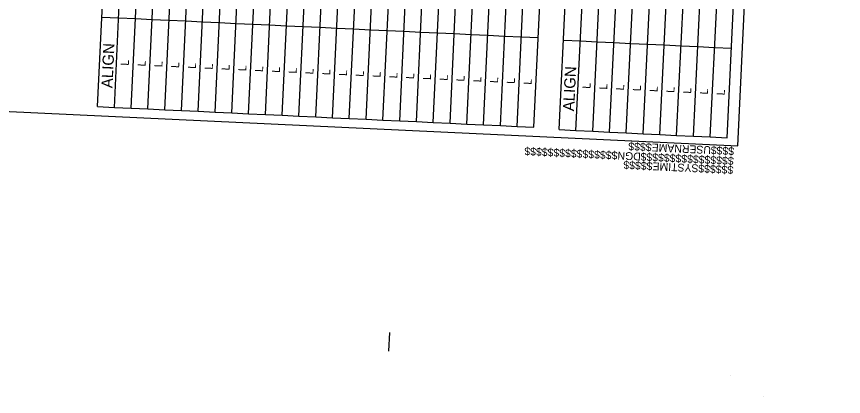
# Model space of a CAD drawing. Extents: x 2167298 to 2168977, y 841960 to 844561.
# Drawn here: x 2168145 to 2168977, y 841960 to 842342 of the extents above; entities that cross this region are included whole.
import ezdxf

# ---------------------------------------------------------------- set-up
doc = ezdxf.new("R2010")
doc.units = 0
for name, color, linetype in [('CTL Sheet Border CELL', 7, 'Continuous'), ('CTL Sheet Notes CELL', 7, 'Continuous'), ('CTL Sheet Table Cell', 7, 'Continuous'), ('CTL Sheet Text', 7, 'Continuous'), ('Sheet Title CELL', 7, 'Continuous')]:
    doc.layers.add(name, color=color, linetype=linetype)

msp = doc.modelspace()

# ---------------------------------------------------------------- linework, layer by layer
at = {"layer": 'CTL Sheet Border CELL'}
for p, q in [((2168863.69, 841981.1), (2168863.69, 841981.1)), ((2168896.39, 841960.04), (2168896.39, 841960.04))]:
    msp.add_line(p, q, dxfattribs=at)
msp.add_lwpolyline([(2167403.66, 844533.83), (2167297.51, 842286.33), (2168870.75, 842212.02), (2168976.9, 844459.52)], close=True, dxfattribs=at)
at = {"layer": 'CTL Sheet Table Cell'}
for p, q in [((2168226.19, 842251.66), (2168255.97, 842882.28)), ((2168243.08, 842250.86), (2168272.86, 842881.48)), ((2168259.97, 842250.06), (2168289.76, 842880.68)), ((2168276.86, 842249.27), (2168306.65, 842879.88)), ((2168293.75, 842248.47), (2168323.54, 842879.09)), ((2168310.65, 842247.67), (2168340.43, 842878.29)), ((2168327.54, 842246.87), (2168357.32, 842877.49)), ((2168344.43, 842246.08), (2168374.21, 842876.69)), ((2168361.32, 842245.28), (2168391.1, 842875.9)), ((2168378.21, 842244.48), (2168408, 842875.1)), ((2168395.1, 842243.68), (2168424.89, 842874.3)), ((2168411.99, 842242.88), (2168441.78, 842873.5)), ((2168428.89, 842242.09), (2168458.67, 842872.7)), ((2168445.78, 842241.29), (2168475.56, 842871.91)), ((2168462.67, 842240.49), (2168492.45, 842871.11)), ((2168479.56, 842239.69), (2168509.35, 842870.31)), ((2168496.45, 842238.9), (2168526.24, 842869.51)), ((2168513.34, 842238.1), (2168543.13, 842868.72)), ((2168530.24, 842237.3), (2168560.02, 842867.92)), ((2168547.13, 842236.5), (2168576.91, 842867.12)), ((2168564.02, 842235.7), (2168593.8, 842866.32)), ((2168580.91, 842234.91), (2168610.69, 842865.52)), ((2168597.8, 842234.11), (2168627.59, 842864.73)), ((2168614.69, 842233.31), (2168644.48, 842863.93)), ((2168631.58, 842232.51), (2168661.37, 842863.13)), ((2168648.48, 842231.72), (2168678.26, 842862.33)), ((2168665.37, 842230.92), (2168695.15, 842861.54)), ((2168690.79, 842228.46), (2168721.52, 842859.03)), ((2168707.68, 842227.63), (2168738.41, 842858.2)), ((2168724.57, 842226.81), (2168755.3, 842857.38)), ((2168741.46, 842225.99), (2168772.19, 842856.56)), ((2168758.35, 842225.16), (2168789.08, 842855.74)), ((2168775.24, 842224.34), (2168805.97, 842854.91)), ((2168792.13, 842223.52), (2168822.86, 842854.09)), ((2168809.02, 842222.69), (2168839.75, 842853.27)), ((2168825.91, 842221.87), (2168856.64, 842852.44)), ((2168842.8, 842221.05), (2168873.53, 842851.62)), ((2168859.69, 842220.22), (2168890.42, 842850.8)), ((2168230.44, 842341.75), (2168247.33, 842340.95)), ((2168247.33, 842340.95), (2168264.23, 842340.15)), ((2168264.23, 842340.15), (2168281.12, 842339.36)), ((2168281.12, 842339.36), (2168298.01, 842338.56)), ((2168298.01, 842338.56), (2168314.9, 842337.76)), ((2168314.9, 842337.76), (2168331.79, 842336.96)), ((2168331.79, 842336.96), (2168348.68, 842336.16)), ((2168348.68, 842336.16), (2168365.58, 842335.37)), ((2168365.58, 842335.37), (2168382.47, 842334.57)), ((2168382.47, 842334.57), (2168399.36, 842333.77)), ((2168399.36, 842333.77), (2168416.25, 842332.97)), ((2168416.25, 842332.97), (2168433.14, 842332.18)), ((2168433.14, 842332.18), (2168450.03, 842331.38)), ((2168450.03, 842331.38), (2168466.92, 842330.58)), ((2168466.92, 842330.58), (2168483.82, 842329.78)), ((2168483.82, 842329.78), (2168500.71, 842328.98)), ((2168500.71, 842328.98), (2168517.6, 842328.19)), ((2168517.6, 842328.19), (2168534.49, 842327.39)), ((2168534.49, 842327.39), (2168551.38, 842326.59)), ((2168551.38, 842326.59), (2168568.27, 842325.79)), ((2168568.27, 842325.79), (2168585.16, 842325)), ((2168585.16, 842325), (2168602.06, 842324.2)), ((2168602.06, 842324.2), (2168618.95, 842323.4)), ((2168618.95, 842323.4), (2168635.84, 842322.6)), ((2168635.84, 842322.6), (2168652.73, 842321.8)), ((2168652.73, 842321.8), (2168669.62, 842321.01)), ((2168695.18, 842318.54), (2168712.07, 842317.71)), ((2168712.07, 842317.71), (2168728.96, 842316.89)), ((2168728.96, 842316.89), (2168745.85, 842316.07)), ((2168745.85, 842316.07), (2168762.74, 842315.25)), ((2168762.74, 842315.25), (2168779.63, 842314.42)), ((2168779.63, 842314.42), (2168796.52, 842313.6)), ((2168796.52, 842313.6), (2168813.41, 842312.78)), ((2168813.41, 842312.78), (2168830.3, 842311.95)), ((2168830.3, 842311.95), (2168847.19, 842311.13)), ((2168847.19, 842311.13), (2168864.08, 842310.31)), ((2168226.19, 842251.66), (2168243.08, 842250.86)), ((2168243.08, 842250.86), (2168259.97, 842250.06)), ((2168259.97, 842250.06), (2168276.86, 842249.27)), ((2168276.86, 842249.27), (2168293.75, 842248.47)), ((2168293.75, 842248.47), (2168310.65, 842247.67)), ((2168310.65, 842247.67), (2168327.54, 842246.87)), ((2168327.54, 842246.87), (2168344.43, 842246.08)), ((2168344.43, 842246.08), (2168361.32, 842245.28)), ((2168361.32, 842245.28), (2168378.21, 842244.48)), ((2168378.21, 842244.48), (2168395.1, 842243.68)), ((2168395.1, 842243.68), (2168411.99, 842242.88)), ((2168411.99, 842242.88), (2168428.89, 842242.09)), ((2168428.89, 842242.09), (2168445.78, 842241.29)), ((2168445.78, 842241.29), (2168462.67, 842240.49)), ((2168462.67, 842240.49), (2168479.56, 842239.69)), ((2168479.56, 842239.69), (2168496.45, 842238.9)), ((2168496.45, 842238.9), (2168513.34, 842238.1)), ((2168513.34, 842238.1), (2168530.24, 842237.3)), ((2168530.24, 842237.3), (2168547.13, 842236.5)), ((2168547.13, 842236.5), (2168564.02, 842235.7)), ((2168564.02, 842235.7), (2168580.91, 842234.91)), ((2168580.91, 842234.91), (2168597.8, 842234.11)), ((2168597.8, 842234.11), (2168614.69, 842233.31)), ((2168614.69, 842233.31), (2168631.58, 842232.51)), ((2168631.58, 842232.51), (2168648.48, 842231.72)), ((2168648.48, 842231.72), (2168665.37, 842230.92)), ((2168690.79, 842228.46), (2168707.68, 842227.63)), ((2168707.68, 842227.63), (2168724.57, 842226.81)), ((2168724.57, 842226.81), (2168741.46, 842225.99)), ((2168741.46, 842225.99), (2168758.35, 842225.16)), ((2168758.35, 842225.16), (2168775.24, 842224.34)), ((2168775.24, 842224.34), (2168792.13, 842223.52)), ((2168792.13, 842223.52), (2168809.02, 842222.69)), ((2168809.02, 842222.69), (2168825.91, 842221.87)), ((2168825.91, 842221.87), (2168842.8, 842221.05)), ((2168842.8, 842221.05), (2168859.69, 842220.22))]:
    msp.add_line(p, q, dxfattribs=at)
at = {"layer": 'Sheet Title CELL'}
msp.add_line((2168519.39, 842005.63), (2168520.25, 842024.36), dxfattribs=at)

# ---------------------------------------------------------------- texts
at = {"layer": 'CTL Sheet Border CELL'}
for s, p in [('$$$$$$$$$$$$$$$$DGN$$$$$$$$$$$$$$$$', (2168866.68, 842200.75)), ('$$$$USERNAME$$$$', (2168867.12, 842210.6)), ('$$$$$$SYSTIME$$$$$', (2168866.25, 842191.69))]:
    msp.add_text(s, height=7.8751, rotation=177.29593, dxfattribs=at).set_placement(p)
at = {"layer": 'CTL Sheet Notes CELL'}
for rotation, p in [(87.29593, (2168241.16, 842269.97)), (87.20981, (2168705.79, 842246.74))]:
    msp.add_text('ALIGN', height=11.274, rotation=rotation, dxfattribs=at).set_placement(p)
at = {"layer": 'CTL Sheet Text'}
for rotation, p in [(87.29593, (2168257.55, 842292.66)), (87.29593, (2168274.44, 842291.86)), (87.29593, (2168291.33, 842291.06)), (87.29593, (2168308.22, 842290.26)), (87.29593, (2168325.12, 842289.47)), (87.29593, (2168342.01, 842288.67)), (87.29593, (2168358.9, 842287.87)), (87.29593, (2168375.79, 842287.07)), (87.29593, (2168392.68, 842286.28)), (87.29593, (2168409.57, 842285.48)), (87.29593, (2168426.46, 842284.68)), (87.29593, (2168443.36, 842283.88)), (87.29593, (2168460.25, 842283.08)), (87.29593, (2168477.14, 842282.29)), (87.29593, (2168494.03, 842281.49)), (87.29593, (2168510.92, 842280.69)), (87.29593, (2168527.81, 842279.89)), (87.29593, (2168544.7, 842279.1)), (87.29593, (2168561.6, 842278.3)), (87.29593, (2168578.49, 842277.5)), (87.29593, (2168595.38, 842276.7)), (87.29593, (2168612.27, 842275.9)), (87.29593, (2168629.16, 842275.11)), (87.29593, (2168646.05, 842274.31)), (87.29593, (2168662.95, 842273.51)), (87.20981, (2168722.21, 842269.41)), (87.20981, (2168739.1, 842268.58)), (87.20981, (2168755.99, 842267.76)), (87.20981, (2168772.88, 842266.94)), (87.20981, (2168789.77, 842266.11)), (87.20981, (2168806.66, 842265.29)), (87.20981, (2168823.55, 842264.47)), (87.20981, (2168840.44, 842263.64)), (87.20981, (2168857.33, 842262.82))]:
    msp.add_text('L', height=8.05, rotation=rotation, dxfattribs=at).set_placement(p)

doc.saveas('drawing.dxf')
